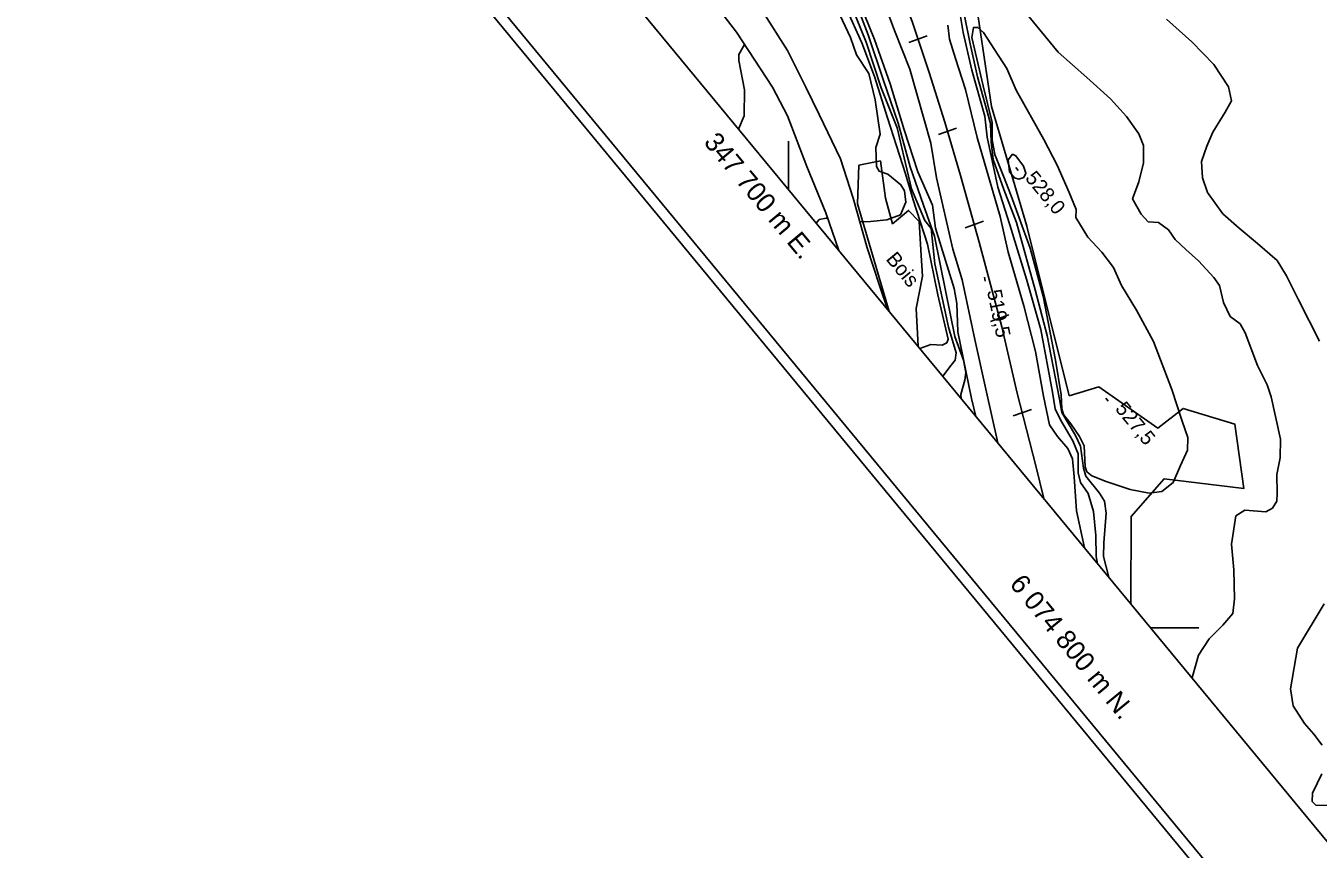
# Model space of a CAD drawing. Extents: x 347312 to 350503, y 6073086 to 6076432.
# Drawn here: x 347542.3 to 347809.5, y 6074754.2 to 6074924.5 of the extents above; entities that cross this region are included whole.
import ezdxf

# ---------------------------------------------------------------- set-up
doc = ezdxf.new("R2010")
doc.units = 0
for name, color, linetype in [('Level 1', 7, 'Continuous'), ('Level 19', 7, 'Continuous'), ('Level 2', 7, 'Continuous'), ('Level 23', 7, 'Continuous'), ('Level 3', 7, 'Continuous'), ('Level 44', 7, 'Continuous'), ('Level 60', 7, 'Continuous'), ('Level 61', 7, 'Continuous')]:
    doc.layers.add(name, color=color, linetype=linetype)

msp = doc.modelspace()

# ---------------------------------------------------------------- linework, layer by layer
at = {"layer": 'Level 1'}
for points in [[(347716.56, 6074937.87), (347721.93, 6074923.47), (347725.08, 6074915.47), (347729.44, 6074900.22), (347730.56, 6074893.04), (347733.95, 6074878.31), (347735.87, 6074871.93), (347738.52, 6074859.63), (347740.83, 6074849.32), (347743.26, 6074838.24)], [(347714.75, 6074883.94), (347716.95, 6074884.02), (347720.3, 6074884.34), (347723.12, 6074885.38), (347724.24, 6074888.01), (347723.96, 6074890.37), (347723.22, 6074891.58), (347720.52, 6074893.77), (347718.73, 6074894.38), (347718.18, 6074895.36), (347718.05, 6074899.27), (347718.95, 6074902.08), (347717.9, 6074909.13), (347716.63, 6074914.58), (347714.08, 6074918.45), (347712.78, 6074922.06), (347710.59, 6074926.75)], [(347761.18, 6074816.54), (347759.56, 6074824.16), (347759.07, 6074831.21), (347758.74, 6074834.93), (347757.76, 6074837.04), (347755.65, 6074839.53), (347753.97, 6074841.98), (347752.74, 6074847.87), (347751.06, 6074857.12), (347748.67, 6074866.57), (347745.42, 6074877.69), (347743.73, 6074885.06), (347739.03, 6074901.35), (347736.61, 6074911.31), (347734.55, 6074917.7), (347733.3, 6074921.7), (347732.97, 6074924.62)], [(347705.74, 6074883.64), (347706.35, 6074884.38), (347707.81, 6074884.68), (347708.18, 6074884.54)]]:
    msp.add_lwpolyline(points, dxfattribs=at)
at = {"layer": 'Level 19'}
for points in [[(347682.99, 6074931.32), (347689.21, 6074923.15), (347696.68, 6074911.8), (347699.77, 6074905.87), (347703.76, 6074895.4), (347707.74, 6074885.82), (347710.43, 6074877.97)], [(347720.45, 6074865.85), (347718.8, 6074870.78), (347716.28, 6074878.57), (347713.35, 6074888.85), (347710.76, 6074896.98), (347706.31, 6074906.14), (347703.6, 6074911.78), (347699.81, 6074919.34), (347694.59, 6074927.47)]]:
    msp.add_lwpolyline(points, dxfattribs=at)
at = {"layer": 'Level 2'}
for points in [[(347704.7, 6074952.12), (347706.75, 6074950.87), (347708.29, 6074948.67), (347709.4, 6074946.63), (347710.28, 6074943.35), (347710.63, 6074938.16), (347711.68, 6074934.3), (347713.98, 6074926.18), (347716.02, 6074921.06), (347719.17, 6074911.66), (347722.47, 6074903.35), (347723.93, 6074897.15), (347725.45, 6074890.78), (347728.17, 6074884.22), (347729.48, 6074882.56), (347730.24, 6074875.28), (347733.09, 6074862.16), (347734.66, 6074856.85)], [(347732.99, 6074859.69), (347730.9, 6074868.84), (347728.75, 6074879.28), (347725.79, 6074888.46), (347724.16, 6074893.84), (347720.46, 6074905.43), (347717.74, 6074913.99), (347715.16, 6074920.96), (347711.88, 6074928.13), (347709.98, 6074933.67), (347709.64, 6074938.15), (347709.8, 6074941.73), (347709.61, 6074945.24)], [(347710.13, 6074946.48), (347711.06, 6074941.93), (347712.81, 6074932.19), (347716.48, 6074922.62), (347719.6, 6074913.17), (347722.68, 6074904.3), (347725.14, 6074895.28), (347727.92, 6074887.41), (347730.19, 6074880.96), (347732.48, 6074869.74), (347734.41, 6074860.21), (347736.16, 6074855.31), (347736.67, 6074852.81), (347736.46, 6074851.17), (347735.63, 6074848.22), (347735.72, 6074847.37)], [(347713.48, 6074932.27), (347717.79, 6074921.64), (347720.98, 6074912.46), (347723.93, 6074902.94), (347726.71, 6074894.24), (347729.74, 6074887.39), (347730.36, 6074882.59), (347734.22, 6074870.14), (347734.83, 6074867.06), (347734.98, 6074861.2), (347737.86, 6074847.39), (347738.75, 6074843.69)], [(347763.91, 6074813.25), (347763.59, 6074814.75), (347763.53, 6074819.08), (347763.08, 6074824.03), (347761.95, 6074827.73), (347760.4, 6074830.03), (347759.92, 6074832.02), (347759.9, 6074835.99), (347758.82, 6074838.68), (347756.23, 6074843.02), (347755.12, 6074845.27), (347754.61, 6074848.71), (347752.17, 6074861.69), (347749.22, 6074872.11), (347745.76, 6074883.3), (347743.31, 6074891.08), (347741.09, 6074901.44), (347740.59, 6074905.81), (347737.92, 6074915.27), (347736.13, 6074923.06), (347735.03, 6074929.72)], [(347766.22, 6074810.45), (347765.15, 6074814.72), (347765.18, 6074817.53), (347765.7, 6074823.68), (347765.33, 6074826.17), (347764.32, 6074827.84), (347761.51, 6074831.32), (347761, 6074833.02), (347760.37, 6074837.54), (347759.33, 6074839.72), (347756.49, 6074844.5), (347756, 6074847.28), (347753.51, 6074860.46), (347750.99, 6074869.89), (347747.11, 6074883.76), (347744.52, 6074890.61), (347742.31, 6074896.85), (347741.89, 6074900.48), (347741.78, 6074904.24), (347739.06, 6074913.9), (347737.55, 6074920.73), (347736.38, 6074926.51)], [(347749.66, 6074926.38), (347755.75, 6074919.02), (347761.66, 6074913.77), (347766.55, 6074909.39), (347769.92, 6074905.72), (347772.43, 6074902.12), (347773.39, 6074899.73), (347773.37, 6074896.14), (347772.46, 6074892.18), (347771.15, 6074888.69)], [(347778.16, 6074925.8), (347783.4, 6074921.17), (347787.92, 6074916.46), (347791, 6074911.87), (347791.62, 6074908.94), (347790.26, 6074906.6), (347787.75, 6074902.49), (347786.49, 6074899.58), (347785.42, 6074896.42)], [(347760.17, 6074839.57), (347758.37, 6074842.17), (347756.88, 6074844.1), (347756.54, 6074845.28), (347756.36, 6074848.17), (347755.23, 6074855.31), (347752.68, 6074868.55), (347749.99, 6074878.49), (347746.01, 6074889.32), (347744.48, 6074893.34), (347742.63, 6074897.88), (347742.09, 6074900.87), (347742.11, 6074904.47), (347740.23, 6074912.03), (347737.91, 6074922.01), (347738.24, 6074924.11), (347739.17, 6074924.13), (347740.31, 6074923.09), (347742.6, 6074919.59), (347745.15, 6074915.64), (347747.08, 6074911.16), (347752.77, 6074900.97), (347755.56, 6074895.62), (347758.04, 6074890.02), (347759.47, 6074886.45), (347759.4, 6074884.8), (347761.87, 6074880.78), (347764.78, 6074877.66), (347767.18, 6074874.5), (347768.88, 6074870.76), (347771.98, 6074865.68), (347775.47, 6074859.2), (347779.24, 6074849.24), (347781.42, 6074842.73), (347782.58, 6074839.32), (347782.5, 6074836.74), (347781.08, 6074833.55), (347779.55, 6074830.01), (347777.23, 6074828.19), (347774.61, 6074827.84), (347770.64, 6074828.61), (347765.65, 6074830.26), (347762.7, 6074831.43), (347761.71, 6074832.25), (347761.37, 6074833.28), (347761.16, 6074837.62), (347760.17, 6074839.57)], [(347690.91, 6074920.57), (347689.73, 6074918.52), (347689.7, 6074917.31), (347690.9, 6074911.19), (347690.8, 6074905.83), (347689.66, 6074903.1)], [(347748.56, 6074895.42), (347749.09, 6074894.01), (347748.65, 6074893.11), (347747.62, 6074892.77), (347746.71, 6074893.06), (347745.66, 6074894.3), (347745.44, 6074896.76), (347746.33, 6074897.9), (347747.02, 6074897.56), (347748.56, 6074895.42)], [(347785.42, 6074896.42), (347785.64, 6074893.02), (347786.61, 6074889.98), (347789.78, 6074885.6), (347793.22, 6074882.64), (347797, 6074879.43), (347801.03, 6074875.91), (347803.01, 6074872.79), (347805.48, 6074867.82), (347809.81, 6074859.23)], [(347771.15, 6074888.69), (347772.9, 6074885.52), (347774.36, 6074883.96), (347776.51, 6074883.77), (347778.55, 6074882.3), (347779.97, 6074880.31), (347782.17, 6074878.18), (347784.79, 6074875.87), (347787.96, 6074872.43), (347789.12, 6074870.75), (347789.97, 6074867.22), (347791.32, 6074864.37), (347793.43, 6074862.82), (347794.43, 6074861), (347796.96, 6074854.24), (347799, 6074850.25), (347799.8, 6074847.73), (347801.73, 6074838.99), (347801.69, 6074835.11), (347800.97, 6074831.71), (347801.07, 6074827.81), (347801, 6074826.16), (347800.09, 6074824.73), (347798.73, 6074823.98), (347794.35, 6074824.28), (347792.52, 6074823.14), (347791.59, 6074817.31), (347792.08, 6074812.01), (347792.22, 6074806.01), (347791.89, 6074802.94), (347789.81, 6074800.53), (347786.97, 6074797.74), (347784.8, 6074794.32), (347783.57, 6074789.95), (347783.44, 6074789.61)], [(347732.99, 6074859.69), (347732.7, 6074858.93), (347731.77, 6074858.41), (347729.43, 6074858.56), (347727.17, 6074857.71)], [(347731.87, 6074852.02), (347733.65, 6074854.27), (347734.46, 6074855.36), (347734.66, 6074856.85)], [(347810.79, 6074804.97), (347805.24, 6074795.77), (347803.8, 6074787.38), (347804.37, 6074783.86), (347806.67, 6074780.2), (347808.65, 6074778.02), (347810.34, 6074775.71)], [(347810.27, 6074769.79), (347808.34, 6074765.77), (347808.27, 6074764.11), (347809.07, 6074763.32), (347811.59, 6074763.23)]]:
    msp.add_lwpolyline(points, dxfattribs=at)
at = {"layer": 'Level 23'}
for p, q in [((347728.67, 6074922.36), (347724.89, 6074921.03)), ((347734.76, 6074903.3), (347730.99, 6074901.97)), ((347740.3, 6074884.05), (347736.52, 6074882.71)), ((347745.53, 6074864.68), (347741.74, 6074863.35)), ((347750.21, 6074845.13), (347746.43, 6074843.79))]:
    msp.add_line(p, q, dxfattribs=at)
msp.add_lwpolyline([(347655, 6075064.72), (347657.04, 6075060.79), (347661.39, 6075053.07), (347668.95, 6075039.21), (347678.13, 6075022.92), (347684.83, 6075011.2), (347695.46, 6074992.01), (347704.02, 6074975.2), (347710.42, 6074962.42), (347716.41, 6074948.61), (347719.4, 6074941.62), (347725.57, 6074925.36), (347729.05, 6074914.83), (347732.3, 6074904.57), (347735.57, 6074893.49), (347739.44, 6074879.71), (347744.12, 6074862.2), (347747.29, 6074848.5), (347751.12, 6074833.48), (347752.77, 6074826.72)], dxfattribs=at)
at = {"layer": 'Level 3'}
for p, q in [((347746.98, 6074895.13), (347747.49, 6074894.51)), ((347740.5, 6074872.46), (347740.66, 6074871.68)), ((347765.6, 6074847.45), (347766.11, 6074846.83))]:
    msp.add_line(p, q, dxfattribs=at)
at = {"layer": 'Level 44'}
for points in [[(347770.76, 6074804.96), (347770.82, 6074823), (347777.67, 6074830.8), (347794.16, 6074828.82), (347792.29, 6074842.11), (347781.58, 6074845.35), (347776.36, 6074841.29), (347764.2, 6074849.83), (347758.05, 6074847.97), (347749.27, 6074883.04), (347741.98, 6074907.79), (347738.16, 6074933.36)], [(347720.8, 6074865.42), (347714.25, 6074887.67), (347714.55, 6074895.62), (347718.99, 6074896.51), (347720.06, 6074888.83), (347721.52, 6074883.54), (347724.83, 6074886.3), (347727.04, 6074884), (347727.45, 6074876.94), (347727.72, 6074872.72), (347726.37, 6074866.04), (347726.77, 6074858.19)]]:
    msp.add_lwpolyline(points, dxfattribs=at)
at = {"layer": 'Level 60'}
for p, q in [((347700, 6074900.59), (347700, 6074890.59)), ((347774.86, 6074800), (347784.86, 6074800))]:
    msp.add_line(p, q, dxfattribs=at)
for points in [[(349159.76, 6073089.49), (347315.28, 6075321.63), (348655.04, 6076428.72), (350499.52, 6074196.58)], [(348779.44, 6073584.28), (350085.28, 6074663.34), (348652.09, 6076397.74), (347346.25, 6075318.68)]]:
    msp.add_lwpolyline(points, close=True, dxfattribs=at)
msp.add_lwpolyline([(347312.14, 6075321.93), (349159.46, 6073086.35)], dxfattribs=at)

# ---------------------------------------------------------------- texts
at = {"layer": 'Level 3'}
for s, rotation, p in [('528,0', 309.5679, (347748.79, 6074892.89)), ('519,5', 281.5083, (347741.04, 6074869.63)), ('527,5', 309.5679, (347767.41, 6074845.21))]:
    msp.add_text(s, height=3, rotation=rotation, dxfattribs=at).set_placement(p)
at = {"layer": 'Level 44'}
msp.add_text('Bois', height=3, rotation=309.568, dxfattribs=at).set_placement((347719.99, 6074876.17))
at = {"layer": 'Level 61'}
for s, rotation, p in [('347 700 m E. ', 309.813, (347682.29, 6074900.31)), ('6 074 800 m N.', 309.3644, (347745.54, 6074808.97))]:
    msp.add_text(s, height=4, rotation=rotation, dxfattribs=at).set_placement(p)

doc.saveas('drawing.dxf')
